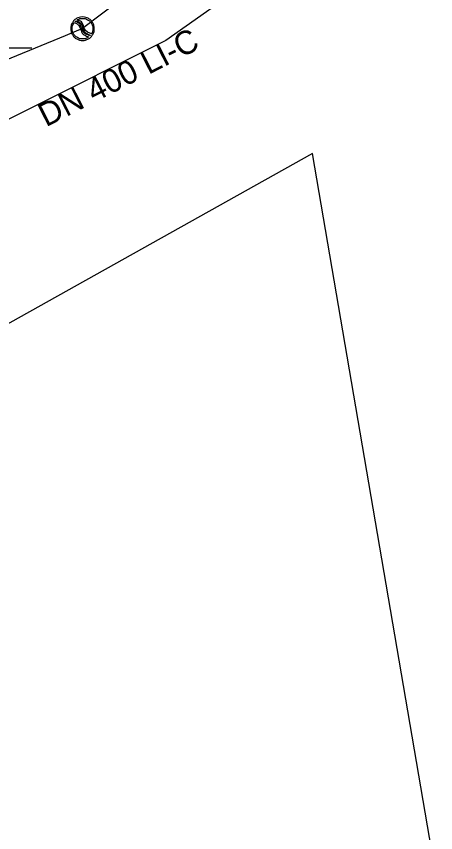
# Model space of a CAD drawing. Extents: x -595844 to -595448, y -1167192 to -1166625.
# Drawn here: x -595641.2 to -595605.5, y -1166863.4 to -1166793.8 of the extents above; entities that cross this region are included whole.
import ezdxf

# ---------------------------------------------------------------- set-up
doc = ezdxf.new("R2010")
doc.units = 0
for name, color, linetype in [('DA V Uzávěr popis', 7, 'Continuous'), ('DA V Řad popis', 7, 'Continuous'), ('Default', 7, 'Continuous'), ('Kanalizační stoka', 7, 'Continuous'), ('V Řad', 7, 'Continuous'), ('Žádost o vyjádření k existenci sítí', 7, 'Continuous')]:
    doc.layers.add(name, color=color, linetype=linetype)

msp = doc.modelspace()

# ---------------------------------------------------------------- linework, layer by layer
at = {"layer": 'DA V Uzávěr popis'}
msp.add_lwpolyline([(-595660.625, -1166819.478), (-595652.386, -1166796.521), (-595639.92, -1166796.521)], dxfattribs=at)
at = {"layer": 'Default'}
for points in [[(-595635.601, -1166793.89), (-595635.349, -1166793.89), (-595635.11, -1166794.019), (-595634.871, -1166794.148), (-595634.735, -1166794.389), (-595634.6, -1166794.629), (-595634.6, -1166794.891), (-595634.6, -1166795.151), (-595634.732, -1166795.389), (-595634.864, -1166795.626), (-595635.102, -1166795.758), (-595635.34, -1166795.89), (-595635.601, -1166795.89), (-595635.86, -1166795.89), (-595636.098, -1166795.758), (-595636.336, -1166795.626), (-595636.468, -1166795.389), (-595636.6, -1166795.151), (-595636.6, -1166794.891), (-595636.6, -1166794.629), (-595636.466, -1166794.389), (-595636.331, -1166794.148), (-595636.093, -1166794.019), (-595635.854, -1166793.89), (-595635.601, -1166793.89)], [(-595636.314, -1166794.381), (-595636.336, -1166794.414), (-595636.357, -1166794.451), (-595636.474, -1166794.661), (-595636.474, -1166794.891), (-595636.474, -1166795.119), (-595636.359, -1166795.326), (-595636.244, -1166795.534), (-595636.035, -1166795.649), (-595635.827, -1166795.765), (-595635.6, -1166795.765), (-595635.371, -1166795.765), (-595635.162, -1166795.649), (-595635.111, -1166795.62), (-595635.065, -1166795.586), (-595635.629, -1166795.395), (-595635.739, -1166794.965), (-595635.921, -1166794.5), (-595636.314, -1166794.381)], [(-595634.965, -1166795.498), (-595634.938, -1166795.469), (-595634.913, -1166795.438), (-595635.458, -1166795.245), (-595635.566, -1166794.825), (-595635.756, -1166794.338), (-595636.179, -1166794.23), (-595636.209, -1166794.257), (-595636.238, -1166794.286), (-595635.838, -1166794.404), (-595635.656, -1166794.872), (-595635.545, -1166795.307), (-595634.965, -1166795.498)], [(-595634.847, -1166795.339), (-595634.843, -1166795.332), (-595634.839, -1166795.326), (-595634.724, -1166795.119), (-595634.724, -1166794.891), (-595634.724, -1166794.661), (-595634.843, -1166794.451), (-595634.961, -1166794.241), (-595635.17, -1166794.128), (-595635.379, -1166794.015), (-595635.6, -1166794.015), (-595635.821, -1166794.015), (-595636.03, -1166794.127), (-595636.046, -1166794.137), (-595636.063, -1166794.146), (-595635.664, -1166794.264), (-595635.482, -1166794.732), (-595635.377, -1166795.146), (-595634.847, -1166795.339)]]:
    msp.add_open_spline(points, degree=3, dxfattribs=at)
at = {"layer": 'Kanalizační stoka'}
for points in [[(-595612.2, -1166777.16), (-595633.856, -1166793.568), (-595635.6, -1166794.89)], [(-595635.6, -1166794.89), (-595637.08, -1166795.497), (-595668.58, -1166808.42)]]:
    msp.add_lwpolyline(points, dxfattribs=at)
at = {"layer": 'V Řad'}
msp.add_lwpolyline([(-595605.917, -1166777.447), (-595605.781, -1166778.2), (-595606.419, -1166779.88), (-595606.968, -1166780.664), (-595621.064, -1166790.636), (-595628.507, -1166795.902), (-595652.125, -1166807.71), (-595656.097, -1166813.885), (-595659.962, -1166819.904)], dxfattribs=at)
at = {"layer": 'Žádost o vyjádření k existenci sítí'}
msp.add_lwpolyline([(-595615.986, -1166805.521), (-595674.806, -1166838.365), (-595648.233, -1166891.812), (-595604.341, -1166873.598)], close=True, dxfattribs=at)

# ---------------------------------------------------------------- texts
at = {"layer": 'DA V Řad popis'}
msp.add_text('DN 400 LI-C', height=2, rotation=27.1009, dxfattribs=at).set_placement((-595638.715, -1166803.306))

doc.saveas('drawing.dxf')
